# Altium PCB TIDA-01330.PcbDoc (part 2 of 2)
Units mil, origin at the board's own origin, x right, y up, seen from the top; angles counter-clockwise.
Board outline 4950 x 3950 mil, 2 copper layers (Top Layer, Bottom Layer), stack 62.2 mil thick; 84 components, 65 nets, 268 pads, 356 vias.
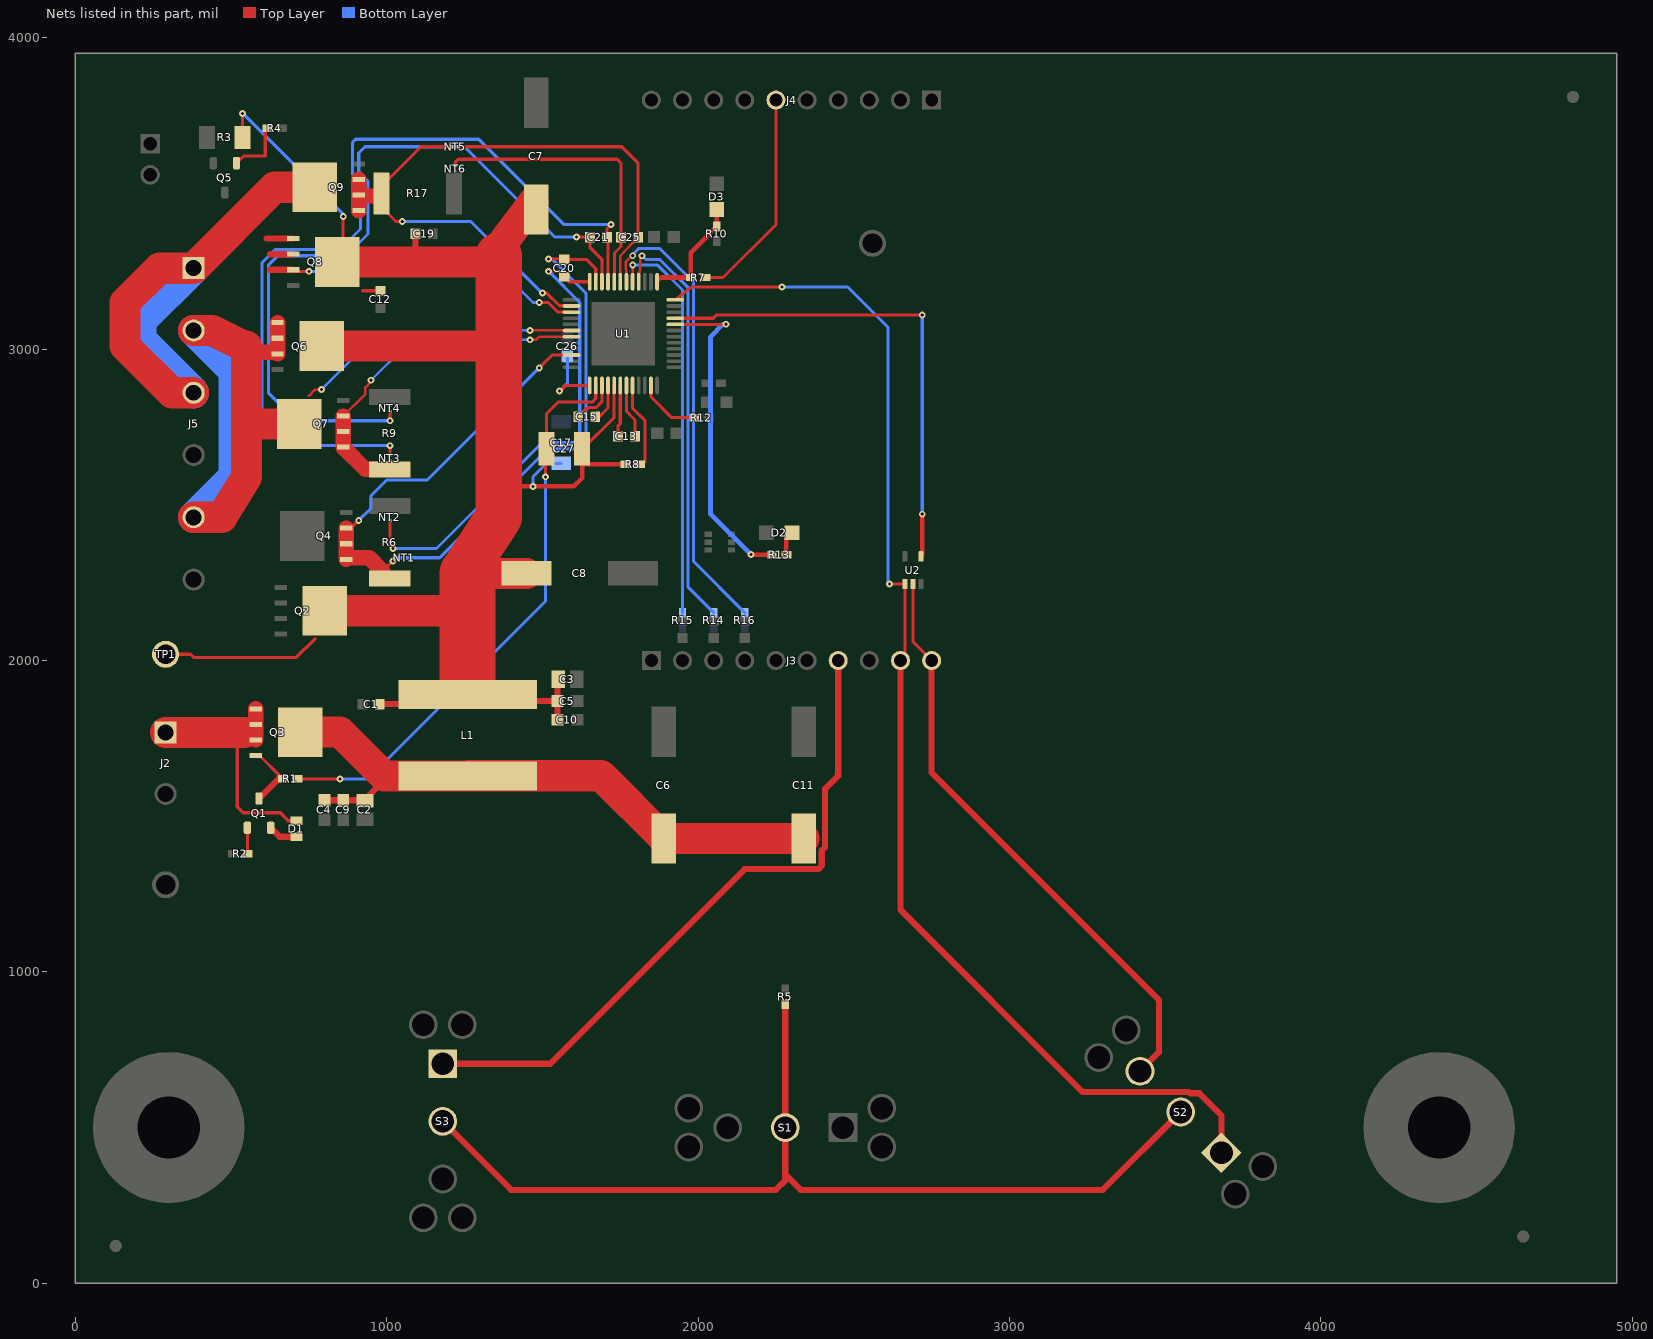
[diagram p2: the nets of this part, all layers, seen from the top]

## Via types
v1: diameter 22, hole 10, Top Layer to Bottom Layer, 318 vias
v2: diameter 19.68, hole 7.87, Top Layer to Bottom Layer, 25 vias
v3: diameter 39.37, hole 19.68, Top Layer to Bottom Layer, 12 vias
v4: diameter 26, hole 10, Top Layer to Bottom Layer, 1 vias

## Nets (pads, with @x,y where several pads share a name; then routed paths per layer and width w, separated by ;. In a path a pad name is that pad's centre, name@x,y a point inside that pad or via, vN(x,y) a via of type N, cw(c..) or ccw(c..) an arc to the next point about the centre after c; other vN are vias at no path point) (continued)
MOT_B: J5.2 J5.5 Q6.1 Q6.2 Q6.3 Q7.5 U1.30 | length 2850
  Top Layer w8: 750,2850 770,2870 v1(790,2870) ; v1(1460,3060) U1.30@1593.5,3060
  Top Layer w50: 520,2990 550,2990 Q6.3@649.57,2990 ; Q6.3@649.57,2985 Q6.2@649.57,3035 Q6.1@649.57,3085
  Top Layer w100: J5.5@380,2460 470,2460 550,2590 ; J5.2@380,3060 440,3060 539.45,3010 ; 550,2600 550,2990 550,3010 ; 560,2760 Q7.5@718.31,2760
  Bottom Layer w8: v1(790,2870) 943.13,3023.13 1356.99,3023.13 1393.86,3060 v1(1460,3060)
  Bottom Layer w100: J5.5@380,2460 510,2590 510,2930 J5.2@380,3060
MOT_C: J5.1 J5.3 Q8.1 Q8.2 Q8.3 Q9.5 U1.27 | length 2902.9
  Top Layer w10: Q8.3@704.57,3250 v1(750,3250) ; v1(1490,3150) 1518.91,3150 1550.01,3118.9 U1.27@1593.66,3118.9 U1.27@1592.76,3119.8
  Top Layer w20: 615,3355 Q8.1@699.57,3355 ; 625,3255 Q8.3@699.57,3255 ; 625,3305 Q8.2@699.57,3305
  Top Layer w100: J5.3@380,2860 310,2860 160,3010 160,3150 270,3260 J5.1@380,3260 640,3520 Q9.5@768.31,3520
  Bottom Layer w10: v1(750,3250) 1370,3250 1470,3150 v1(1490,3150)
  Bottom Layer w100: J5.3@380,2860 210,3030 210,3090 J5.1@380,3260
NetC13_1: C13.1 U1.43 | length 175.1
  Top Layer w10: U1.43@1769.84,2883.66 1769.84,2800.16 1797.56,2772.44 C13.1@1797.56,2720
NetC13_2: C13.2 U1.42 | length 166.9
  Top Layer w10: C13.2@1742.44,2720 1742.44,2752.44 1750.16,2760.16 U1.42@1750.16,2883.66
NetC15_1: C15.1 U1.39 | length 148.9
  Top Layer w10: C15.1@1614.88,2782.44 1642.44,2810 1646.87,2810 1648.92,2812.05 1672.05,2812.05 1691.1,2831.1 U1.39@1691.1,2883.66
NetC15_2: C15.2 U1.40 | length 125.4
  Top Layer w10: C15.2@1670,2782.44 1682.44,2782.44 1710.79,2810.79 U1.40@1710.79,2883.66
NetC26_1: C26.1 U1.37 | length 227.5
  Top Layer w10: v1(1555.28,2865.28) 1573.66,2883.66 U1.37@1651.73,2883.66
  Bottom Layer w10: v1(1555.28,2865.28) 1580,2890 C26.1@1580,2978.5
NetD1_2: D1.2 Q1.2 | length 94.3
  Top Layer w20: Q1.2@627.4,1462.76 655.75,1434.41 D1.2@710,1434.41
NetD2_2: D2.2 R13.2 | length 52.3
  Top Layer w15: R13.2@2283.62,2340 D2.2@2283.62,2392.28
NetQ1_1: Q1.1 R2.1 | length 81.7
  Top Layer w10: R2.1@552.6,1381.02 Q1.1@552.6,1462.76
NetQ1_3: Q1.3 Q3.4 R1.2 | length 197
  Top Layer w10: Q3.4@579.57,1695 591.38,1695 R1.2@659.57,1626.81
  Top Layer w20: Q1.3@590,1557.24 R1.2@652.76,1620
NetQ5_1: Q5.1 R4.2 | length 198.4
  Top Layer w10: Q5.1@517.4,3597.24 540.16,3620 610,3620 610,3710 R4.2@616.38,3710
NetR5_2: R5.2 S1.2 S2.2 S3.2 | length 3164.2
  Top Layer w20: S3.2@1180,520 1400,300 2250,300 2280,330 2280,350 ; R5.2@2280,896.38 S1.2@2280,500 2280,350 ; S2.2@3550,550 3300,300 2330,300 2280,350
NetR8_1: R8.1 U1.44 | length 274.6
  Top Layer w10: U1.44@1789.53,2883.66 1789.53,2810.47 1830,2770 1830,2640 R8.1@1820,2630
NetR14_2: R14.2 U1.16 | length 1359
  Top Layer w8: U1.16@1811.12,3218.24 U1.16@1809.21,3216.34 1809.21,3244.44 1812.93,3248.15 1812.93,3253.74 1813.83,3254.65 1813.83,3293.83 v1(1820,3300)
  Bottom Layer w10: v1(1820,3300) 1832.13,3287.87 1877.4,3287.87 1967.87,3197.4 1967.87,2235.75 R14.2@2050,2153.62
NetR15_2: R15.2 U1.17 | length 1285.4
  Top Layer w8: v1@1789.53,3269.53 U1.17@1789.53,3216.34 U1.17@1791.43,3218.24
  Bottom Layer w10: v1(1790,3270) 1870,3270 1950,3190 R15.2@1950,2153.62
NetR16_2: R16.2 U1.18 | length 1480.2
  Top Layer w8: U1.18@1771.75,3218.24 U1.18@1769.84,3216.34 1769.84,3255.09 1767.13,3257.81 1767.13,3279.47 1787.65,3300 v1(1790,3300)
  Bottom Layer w10: v1(1790,3300) 1790,3303.76 1810.11,3323.87 1876.13,3323.87 1985.75,3214.25 1985.75,2317.87 R16.2@2150,2153.62
NFAULT: R13.1 U1.8 | length 1050.1
  Top Layer w10: U1.8@1926.34,3079.53 v1@2089.53,3079.53
  Top Layer w15: v1(2170,2340) R13.1@2236.38,2340
  Bottom Layer w15: v1(2090,3080) 2079.84,3080 2040,3040.16 2040,2470 v1(2170,2340)
NRESET: J4.6 R7.2 | length 696.8
  Top Layer w10: R7.2@2023.62,3230 2080,3230 2250,3400 J4.6@2250,3800
NSCS: U1.9 U2.4 | length 1575.7
  Top Layer w10: U1.9@1926.34,3099.21 2049.21,3099.21 2060,3110 v1(2720,3110)
  Top Layer w15: U2.4@2715.59,2334.29 2720,2338.7 v1(2720,2470)
  Bottom Layer w10: v1(2720,2470) v1(2720,3110)
PVDD: C1.1 C3.1 C5.1 C7.1 C8.1 C10.1 C12.1 C17.1 C19.1 C27.2 L1.2 Q2.5 Q6.5 Q8.5 R3.1 R8.2 TP1.1 U1.41 | length 6091.8
  Top Layer w10: TP1.1@290,2020 370,2020 380,2010 710,2010 770,2070 ; R3.1@537.09,3680 v1(537.09,3757.09) ; Q8.5@860,3298.31 860,3426.24 v1(860.56,3425.68) ; 922.44,3187.56 C12.1@980,3187.56 ; C27.2@1627.75,2679.34 C27.2@1627.09,2680 1630,2680 1730.47,2780.47 U1.41@1730.47,2883.66
  Top Layer w15: 1369.19,2559.19 v1(1470,2559.19) 1600.81,2559.19 1627.75,2586.13 ; 1627.75,2590 C27.2@1627.75,2679.34 ; C27.2@1627.75,2630 R8.2@1766.38,2630
  Top Layer w20: C1.1@977.56,1860 L1.2@1229.09,1860 ; 1092.44,3287.56 C19.1@1092.44,3370 ; L1.2@1280.91,1870 C5.1@1548.5,1870 ; C10.1@1548.5,1810 C5.1@1548.5,1870 ; C3.1@1550.47,1940 1548.5,1938.03 C5.1@1548.5,1870
  Top Layer w100: Q6.5@791.69,3010 1350,3010 ; Q2.5@801.69,2160 1260,2160 ; Q8.5@841.69,3280 1340,3280 ; 1260,2280 C8.1@1448.74,2280 ; 1380,3350 C7.1@1470,3470
  Top Layer w150: 1250,2290 1360,2460 1360,3300
  Top Layer w180: 1260,1940 1260,2160 1260,2280
  Bottom Layer w10: v1(537.09,3757.09) 860.56,3433.61 v1(860.56,3425.68) ; v1(1470,2559.19) 1470,2590 1513.07,2633.07 C17.1@1560,2633.07
PWRGD: D3.1 R7.1 R10.1 U1.13 | length 368.3
  Top Layer w10: U1.13@1868.27,3216.34 1881.93,3230
  Top Layer w15: 1881.93,3230 R7.1@1976.38,3230 1976.38,3310 2032.82,3366.44 2032.82,3368.49 2057.94,3393.62 R10.1@2060,3393.62 D3.1@2060,3448.66
S1_N: C20.1 NT1.1 U1.23 | length 1575.2
  Top Layer w10: v1(1520,3290) C20.1@1567.56,3290 ; C20.1@1570,3287.56 1642.44,3287.56 1671.42,3258.58 U1.23@1671.42,3216.34
  Bottom Layer w10: NT1.1@1066.31,2330 1170,2330 1510,2671.72 1510,2680 1610,2680 1610,2681.72 1640,2711.72 1640,3180 1530,3290 v1(1520,3290)
S1_P: C20.2 NT2.1 U1.24 | length 1558.8
  Top Layer w10: NT2.1@1010,2450 1010,2370 v1(1020,2360) ; v1(1520,3250) 1552.44,3250 C20.2@1570,3232.44 1586.1,3216.34 U1.24@1650.14,3216.34
  Bottom Layer w10: v1(1020,2360) 1160,2360 1470,2670 1500,2700 1600,2700 1620,2720 1620,3150 v1(1520,3250)
S2_N: C21.1 NT3.1 U1.21 | length 2774.6
  Top Layer w10: NT3.1@1010,2660 v1(1010,2690) ; U1.21@1711.1,3210.59 1711.1,3356.46 C21.1@1707.56,3360 1707.56,3387.56 v1(1720,3400)
  Bottom Layer w10: v1(1010,2690) 680,2690 600,2770 600,3278.28 641.72,3320 850,3320 915.86,3385.86 915.86,3535.86 890,3561.72 890,3664.14 900,3674.14 1295.86,3674.14 1570,3400 v1(1720,3400)
S2_P: C21.2 NT4.1 U1.22 | length 2531.6
  Top Layer w10: v1(1010,2770) NT4.1@1010,2800 ; v1(1610,3360) C21.2@1652.44,3360 1652.44,3327.56 1691.1,3288.9 U1.22@1691.1,3216.34
  Bottom Layer w10: v1(1010,2770) 710,2770 620,2860 620,3270 650,3300 870,3300 940,3370 940,3540 910,3570 910,3630 930,3650 1250,3650 1540,3360 v1(1610,3360)
S3_N: C25.1 NT5.1 U1.19 | length 1001.5
  Top Layer w8: U1.19@1750.16,3216.34 1750.16,3298.78 ; 1751.38,3300 C25.1@1807.56,3360
  Top Layer w10: NT5.1@1230,3650 1755.12,3650 1807.56,3597.56 C25.1@1807.56,3360
S3_P: C25.2 NT6.1 U1.20 | length 940.8
  Top Layer w10: NT6.1@1220,3590 1220,3600 1230,3610 1740,3610 1752.44,3597.56 C25.2@1752.44,3360 1752.44,3329.69 1731.38,3308.62 U1.20@1731.38,3217.24
SL_A: NT1.2 Q4.1 Q4.2 Q4.3 R6.2 U1.34 | length 1290.6
  Top Layer w10: Q4.3@870.43,2425 885,2425 v1(910,2450) ; R6.2@986.93,2286.93 v1(1020,2320) ; v1(1490,2940) 1531.1,2981.1 U1.34@1593.66,2981.1
  Top Layer w50: Q4.3@870.43,2425 Q4.2@870.43,2375 Q4.1@870.43,2325 875.43,2330 943.86,2330 R6.2@986.93,2286.93
  Bottom Layer w10: v1(910,2450) 950,2490 950,2530 1000,2580 1130,2580 v1(1490,2940) ; v1(1020,2320) 1030,2330 NT1.2@1046.31,2330
SL_B: NT3.2 Q7.1 Q7.2 Q7.3 R9.2 U1.31 | length 1132.9
  Top Layer w8: Q7.3@860.43,2785 931.2,2855.76 931.2,2876.65 950,2895.45 v1(950,2900) ; v1(1460,3030) 1480,3030 1490.16,3040.16 U1.31@1593.66,3040.16
  Top Layer w50: Q7.3@860.43,2785 Q7.2@860.43,2735 Q7.1@860.43,2685 931.57,2613.86 R9.2@1010,2613.86
  Bottom Layer w8: v1(950,2900) 1057.25,3007.25 1363.56,3007.25 1386.31,3030 v1(1460,3030)
SL_C: NT5.2 Q9.1 Q9.2 Q9.3 R17.2 U1.26 | length 1213.3
  Top Layer w10: R17.2@983.86,3456.14 1030,3410 v1(1050,3410) ; R17.2@983.86,3500 983.86,3523.86 1110,3650 NT5.2@1210,3650 ; v1(1500,3180) 1514.18,3180 1554.7,3139.49 1592.76,3139.49 U1.26@1593.66,3138.58
  Top Layer w50: Q9.1@910.43,3445 Q9.2@910.43,3495 ; Q9.3@910.43,3545 Q9.2@910.43,3495 ; R17.2@980,3490 Q9.2@910.43,3495
  Bottom Layer w10: v1(1050,3410) 1270,3410 v1(1500,3180)
TILT+: J3.9 S2.1 U1.12 U2.1 | length 4104.3
  Top Layer w10: U1.12@1926.34,3158.27 1980,3200 v1(2270,3200) ; v1(2614.29,2245.71) U2.1@2664.41,2245.71 2664.41,2014.41 J3.9@2650,2000
  Top Layer w20: J3.9@2650,2000 2650,1200 3235.87,614.13 3576.57,614.13 3580.7,610 3610,610 3680.84,539.16 S2.1@3680.84,419.16
  Bottom Layer w10: v1(2270,3200) 2480,3200 2610,3070 2610,2250 v1(2614.29,2245.71)
TILT-: J3.10 S2.3 U2.2 | length 1917.3
  Top Layer w10: U2.2@2690,2245.71 2690,2060 J3.10@2750,2000
  Top Layer w20: J3.10@2750,2000 2750,1640 3480,910 3480,741.69 S2.3@3419.16,680.84
UP: J3.7 S3.1 | length 2161.7
  Top Layer w20: S3.1@1180,705.04 1525.04,705.04 2150.16,1330.16 2386.77,1330.16 2397.24,1340.63 2397.24,1390 2407.87,1400.63 2407.87,1587.87 2450,1630 J3.7@2450,2000
VBATT: D1.1 J2.1 Q3.1 Q3.2 Q3.3 | length 776.8
  Top Layer w10: 520,1745.91 520,1530 539.02,1510.98 657.91,1510.98 683.31,1485.59 D1.1@710,1485.59
  Top Layer w50: Q3.3@579.57,1745 Q3.2@579.57,1795 Q3.1@579.57,1845
  Top Layer w100: J2.1@290,1768.43 542.52,1768.43
VCPH: C27.1 R1.1 U1.38 | length 1853.3
  Top Layer w10: R1.1@713.62,1620 v1(850,1620) ; v1(1510,2590) C27.1@1510,2677.09 ; C27.1@1512.91,2680 1512.91,2792.91 1550,2830 1660,2830 1671.42,2841.42 U1.38@1671.42,2883.66
  Bottom Layer w10: v1(850,1620) 940,1620 1510,2190 v1(1510,2590)
VFILT: C2.1 C4.1 C6.1 C9.1 C11.1 L1.1 Q3.5 | length 1990.8
  Top Layer w20: C4.1@800,1551.5 C9.1@860,1551.5 928.03,1551.5 990.91,1614.37 990.91,1629.09
  Top Layer w100: Q3.5@721.69,1770 850,1770 990.91,1629.09 L1.1@1260,1629.09 ; L1.1@1260.91,1630 1688.74,1630 C6.1@1890,1428.74 C11.1@2340,1428.74
WAKE: R12.1 U1.47 | length 202.4
  Top Layer w10: U1.47@1848.58,2883.66 1848.58,2846.69 1915.28,2780 R12.1@1986.38,2780
pads on no net: D4.4 FID1.1 FID2.1 FID3.1 J4.7 MH1.1 MH2.1 S1.S1 S1.S2 S1.S3 S1.S4 S2.S1 S2.S2 S2.S3 S2.S4 S3.S1 S3.S2 S3.S3 S3.S4
copper on no net:
  other v3: 300,341.54 4380,341.54 162.77,420.77 437.23,420.77 4242.77,420.77 4517.23,420.77 162.77,579.23 437.23,579.23 4242.77,579.23 4517.23,579.23 300,658.46 4380,658.46

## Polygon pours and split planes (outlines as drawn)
GND on Bottom Layer "BOTTOM_LAYER_GND_P008" (solid, remove dead copper, pour order 8): 50,50 4900,50 4900,3900 50,3900 50,50
GND on Top Layer "TOP_LAYER_GND_P020" (solid, remove dead copper, pour order 20): 10,10 10,3940 4940,3940 4940,10 10,10
MOT_C on Top Layer "TOP_LAYER_MOT_C_P018" (solid, remove dead copper, pour order 18): 660,3370 660,3240 410,3240 550,3370

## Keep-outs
Keep-Out Layer:
  text ".Layer_Name" at 577,-858.49 h60

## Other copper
Top Layer:
  text ".Layer_Name" at 577,-858.49 h60
Bottom Layer:
  text ".Layer_Name" at 577,-858.49 h60

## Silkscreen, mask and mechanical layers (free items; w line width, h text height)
Top Overlay:
  region: 4120,3160 3820,3160 3820,3060 4120,3060
  lines w10: 100,1360 2780,1360 ; 100,1880 100,3470 ; 100,3860 2790,3860 2790,3720 2790,1360
  text "-LED+" at 90,3520 h72.83 r90
  text "TIDA-01330" at 3040,3070 h150
  text "+" at 50,1750 h100
  text "-" at 50,1550 h100
  text ".Layer_Name" at 577,-858.49 h60
Bottom Overlay:
  text ".Layer_Name" at 577,-858.49 h60
Top Paste:
  text ".Layer_Name" at 577,-858.49 h60
Bottom Paste:
  text ".Layer_Name" at 577,-858.49 h60
Top Solder:
  text ".Layer_Name" at 577,-858.49 h60
  text ".Layer_Name" at 577,-858.49 h60
Bottom Solder:
  text ".Layer_Name" at 577,-858.49 h60
Drill Guide:
  text ".Layer_Name" at 577,-858.49 h60
M1 Board Outline:
  the board outline again, w10
  text ".Layer_Name" at 577,-858.49 h60
M2 Board Dimensions:
  rectangle: 125,-400 500,-275
  rectangle: 0,-275 125,-150
  lines w7: 0,-275 1000,-275 ; 125,-400 125,-150 ; 250,-400 250,-150 ; 500,-400 500,-150 ; 750,-400 750,-150 ; 0,-400 0,-150 1000,-150 1000,-400 0,-400
  lines w10: 4950,0 4950,3940
  text ".Layer_Name" at 577,-858.49 h60
M3 3D STEP Top:
  text ".Layer_Name" at 577,-858.49 h60
M4 3D STEP Bottom:
  text ".Layer_Name" at 577,-858.49 h60
M5 Assembly Top:
  lines w10: -292,-930.17 6308,-930.17 ; -292,-726.83 6310,-726.83 ; -292,-523.5 -292,-1133.5 3713,-1133.5 6310,-1133.5 6310,-523.5 -291.5,-523.5 -291.5,-1133.5 1284,-1133.5 ; 2173,-1133.5 2173,-523.5 ; 3440,-726.83 3440,-523.5 ; 4280,-726.83 4280,-523.5 ; 4902,-1140 4902,-937.17
  text "COMPONENTS MARKED 'DNP' SHOULD NOT BE POPULATED." at 1153.5,-318.5 h60
  text "ASSEMBLY VARIANT:" at 1153,-434 h60
  text ".VariantName" at 2189,-434 h60
  text "PCB VIEWED FROM TOP SIDE" at -228.5,-655.67 h60
  text "BOARD #:" at 2248,-655.67 h60
  text ".PRJ_Number" at 2793.5,-655.67 h60
  text "REV:" at 3638,-655.67 h60
  text ".PCB_Rev" at 3929.5,-655.67 h60
  text "SVN REV:" at 4476,-655.67 h60
  text ".VersionControl_RevNumber" at 4982,-655.67 h60
  text "TID #:" at 2248,-859 h60
  text ".TID" at 2793.5,-859 h60
  text "PLOT NAME =" at -228.5,-1064.34 h60
  text ".plot_File_Name" at 577,-1064.34 h60
  text "GENERATED    :" at 2250,-1064.34 h60
  text ".Print_Date" at 3119.5,-1064.34 h60
  text ".Print_Time" at 3848.5,-1064.34 h60
  text "TEXAS INSTRUMENTS" at 5113,-1064.34 h60
M6 Assembly Bottom:
  lines w10: -292.5,-727.33 6309.5,-727.33 ; -290.5,-930.67 6309.5,-930.67 ; 1115.5,-1140.5 1115.5,-937.67 ; 1737.5,-727.33 1737.5,-524 ; 2577.5,-727.33 2577.5,-524 ; 3844.5,-1134 3844.5,-524 ; 4733.5,-1134 6309,-1134 6309,-524 -292.5,-524 -292.5,-1134 2304.5,-1134 6309.5,-1134 6309.5,-524
  text "COMPONENTS MARKED 'DNP' SHOULD NOT BE POPULATED." at 6102,-318 h60
  text ".VariantName" at 5058,-434 h60
  text "ASSEMBLY VARIANT:" at 6097,-434 h60
  text ".VersionControl_RevNumber" at 1035.5,-656.17 h60
  text "SVN REV:" at 1541.5,-656.17 h60
  text ".PCB_Rev" at 2088,-656.17 h60
  text "REV:" at 2379.5,-656.17 h60
  text ".PRJ_Number" at 3224,-656.17 h60
  text "BOARD #:" at 3769.5,-656.17 h60
  text "PCB VIEWED FROM BOTTOM SIDE" at 6246,-656.17 h60
  text ".TID" at 3224,-859.5 h60
  text "TID #:" at 3769.5,-859.5 h60
  text "TEXAS INSTRUMENTS" at 904.5,-1064.84 h60
  text ".Print_Time" at 2169,-1064.84 h60
  text ".Print_Date" at 2898,-1064.84 h60
  text "GENERATED    :" at 3767.5,-1064.84 h60
  text ".plot_File_Name" at 5440.5,-1064.84 h60
  text "PLOT NAME =" at 6246,-1064.84 h60
M9 Title Sheet:
  drawing of 57 lines, arcs and shapes, not listed
  text "1" at 739.84,8036.5 h70
  text "2" at 3235.5,8036.5 h70
  text "3" at 5724.84,8036.5 h70
  text "4" at 8231.51,8036.5 h70
  text "5" at 10730.5,8036.5 h70
  text "6" at 13235.5,8036.5 h70
  text "A" at -416.5,6893.5 h70
  text "A" at 14383.5,6893.5 h70
  text "B" at -416.5,4513.5 h70
  text "B" at 14383.5,4513.5 h70
  text "C" at -416.5,2138.5 h70
  text "C" at 14383.5,2138.5 h70
  text "PROJECT TITLE:" at 11343.5,277.5 h45
  text ".PRJ_Title" at 11393.5,144.17 h70
  text "DESIGNED FOR:" at 11343.5,-23.5 h45
  text ".PRJ_Customer" at 11393.5,-163.5 h70
  text "D" at -416.5,-231.5 h70
  text "D" at 14383.5,-231.5 h70
  text "FILE NAME:" at 11343.5,-323.5 h45
  text ".PCB_File_Name_No_Path" at 11393.5,-443.5 h70
  text "Texas Instruments (TI) and/or its licensors do not warrant the accuracy or completeness of this specification" at 6374,-605.34 h45
  text "ENGINEER:" at 11343.5,-613.5 h45
  text "LAYOUT BY:" at 12848.5,-613.5 h45
  text "or any information contained therein. TI and/or its licensors do not warrant that this design will meet" at 6329.01,-718 h45
  text ".PRJ_Engineer" at 11393.5,-768.49 h70
  text ".PCB_Layout" at 12899,-768.49 h70
  text "the specifications, will be suitable for your application or fit for any particular purpose, or will operate in" at 6329.01,-830.67 h45
  text ".Layer_Name" at 577,-858.49 h60
  text "ALTIUM DESIGNER VERSION:" at 12848.5,-923.5 h45
  text "an implementation. TI and/or its licensors do not warrant that the design is production worthy. You should" at 6329.01,-943.33 h45
  text "completely validate and test your design implementation to confirm the system functionality for your application." at 6374,-1056 h45
  text ".print_Scale" at 11393.5,-1056.83 h70
  text ".Application_BuildNumber" at 12899,-1056.83 h70
  text "1" at 739.84,-1263.5 h70
  text "2" at 3235.5,-1263.5 h70
  text "3" at 5724.84,-1263.5 h70
  text "4" at 8231.51,-1263.5 h70
  text "5" at 10730.5,-1263.5 h70
  text "6" at 13235.5,-1263.5 h70
M10 Fab Notes:
  drawing of 173 lines, arcs and shapes, not listed
  text "DESIGN INFORMATION" at 12378.02,6201 h60
  text "MIN. TRACK WIDTH:" at 11733.46,6021 h60
  text "8" at 12829.7,6021 h60
  text "MIL" at 12984.46,6021 h60
  text "MIN. CLEARANCE:" at 11733.46,5889 h60
  text "0.2" at 12769.7,5889 h60
  text "mm" at 12984.46,5889 h60
  text "MIN. VIA PAD SIZE:" at 11733.46,5757 h60
  text "24" at 12799.71,5757 h60
  text "MIL" at 12984.46,5757 h60
  text "0.05mm (2MIL)" at 12428.46,5615.29 h60
  text "MINIMUM ANNULAR RING" at 11404.23,5611 h60
  text "EXTERNAL" at 13136.46,5611 h60
  text "PER" at 11604.23,5493 h60
  text "IPC-D-275 CLASS 2 LEVEL C" at 11824.23,5493 h60
  text "MIL, HOLES" at 13312.46,5380.71 h60
  text "+/-" at 12920,5380 h60
  text "+/-" at 13774,5380 h60
  text "REGISTRATION TOLERANCES:" at 11404.23,5375 h60
  text "METAL" at 12604,5375 h60
  text "5" at 13180.2,5375 h60
  text "3" at 14013.2,5375 h60
  text "MIL" at 14129.46,5375 h60
  text "+/-" at 13774,5262 h60
  text "HOLE SIZE TOLERANCE (UNLESS OTHERWISE SPECIFIED):" at 11404.23,5257 h60
  text "3" at 14013.2,5257 h60
  text "MIL" at 14129.46,5257 h60
  text "MATERIAL:" at 11329.46,5047.54 h60
  text "FR-4 High Tg" at 12315.9,4907.21 h60
  text "FR-408" at 11750.46,4898.64 h60
  text "OTHER" at 13238.46,4898.64 h60
  text "X" at 12161,4895 h60
  text "62 MIL (1.6mm) +/-10%" at 12070.56,4735.92 h60
  text "THICKNESS:" at 11404.23,4731.64 h60
  text "X" at 11942.4,4731.64 h60
  text "OTHER" at 13355.46,4731.64 h60
  text "TOLERANCE:" at 11404.23,4573.64 h60
  text "X" at 12243.53,4573.64 h60
  text "ANSI IPC-6012 TYPE 3 CLASS 2" at 12430.48,4573.64 h60
  text "OTHER +/-" at 12430.46,4417.64 h60
  text "BOW & TWIST:" at 11404.23,4260.64 h60
  text "X" at 12243.53,4260.64 h60
  text "ANSI IPC-6012 TYPE 3 CLASS 2" at 12430.48,4260.64 h60
  text "OTHER +/-" at 12430.46,4102.13 h60
  text "DRILLING:" at 11329.46,3963.64 h60
  text "REFERENCE:" at 11404.23,3846.64 h60
  text "X" at 12052.46,3846.64 h60
  text "AS SHOWN" at 12239.46,3846.64 h60
  text "X" at 12953.46,3846.64 h60
  text "NC_DRILL FILES" at 13090.46,3846.64 h60
  text "PTH COPPER THICKNESS:" at 11404.23,3688.64 h60
  text "X" at 12534.46,3688.64 h60
  text "20-30 um" at 12671.46,3688.64 h60
  text "OTHER" at 13388.46,3688.64 h60
  text "BOARD FINISH:" at 11329.46,3529.64 h60
  text "SILKSCREEN:" at 11484.68,3411.64 h60
  text "X" at 12433.46,3411.64 h60
  text "TOP" at 12559.46,3411.64 h60
  text "X" at 12943.46,3411.64 h60
  text "BOTTOM" at 13070.46,3411.64 h60
  text "SILKSCREEN COLOR:" at 11484.68,3244.64 h60
  text "X" at 12432.42,3244.64 h60
  text "WHITE" at 12559.46,3244.64 h60
  text "OTHER" at 13070.46,3244.64 h60
  text "X" at 12563.42,3085.44 h60
  text "GREEN" at 12690.46,3085.44 h60
  text "OTHER" at 13308.46,3085.44 h60
  text "SOLDER RESIST COLOR:" at 11484.68,3074.64 h60
  text "X" at 12563.42,2915.44 h60
  text "MATTE" at 12690.46,2915.44 h60
  text "SEMI-GLOSS" at 13308,2914.8 h60
  text "IMMERSION GOLD (ENIG)" at 12390.46,2726.92 h60
  text "ENEPIG" at 13728,2723.64 h60
  text "SURFACE FINISH:" at 11329.46,2722.64 h60
  text "X" at 12203.51,2722.64 h60
  text "IMM. TIN/SILVER OR EQUIV" at 11659,2565.64 h60
  text "OTHER" at 13090.46,2565.64 h60
  text "ARRAY/PANEL:" at 11329.46,2386.64 h60
  text "CUT AND TRIM PER M1 BOARD OUTLINE" at 12390.46,2382.35 h60
  text "N.C. ROUTE" at 12390.46,2230.64 h60
  text "X" at 13069.46,2230.64 h60
  text "V. SCORE" at 13256.46,2230.64 h60
  text "CERTIFICATION:" at 11329.46,2093.64 h60
  text "MATERIALS AND WORKMANSHIP FOR ALL PCBS" at 12054.46,2093.64 h60
  text "TO MEET OR EXCEED THE REQUIREMENTS OF:" at 12054.46,1995.64 h60
  text "X" at 11680.96,1859.13 h60
  text "ANSI IPC-A-600F CLASS ->" at 11819.96,1859.13 h60
  text "X" at 13459.02,1859.13 h60
  text "2" at 13577.96,1859.14 h60
  text "1" at 13262.96,1857.64 h60
  text "3" at 13931.96,1857.64 h60
  text "X" at 12495.02,1699.64 h60
  text "RoHS" at 12631.96,1699.64 h60
  text "OTHER" at 13276.36,1699.64 h60
  text "PER ORDER" at 13673.42,1699.64 h60
  text "ALL BOARDS MUST MEET OR EXCEED UL94-V0 REQUIREMENTS." at 11357,1534 h60
  text "PCB MUST BEAR THE UL94V-0 UL REGISTERED MATERIAL ID NUMBER" at 11357,1414 h60
  text "ADDITIONAL REQUIREMENTS:" at 11329.46,1240.64 h60
  text "MICROSECTION:" at 11404.23,1125.64 h60
  text "YES" at 12309.96,1125.64 h60
  text "REQUIRED" at 13171.46,969.49 h60
  text "BARE BOARD ELEC. TEST:" at 11404.23,966.64 h60
  text "NONE" at 12709.96,966.64 h60
  text "X" at 13044.46,966.64 h60
  text "PER ORDER" at 13763.46,966.64 h60
  text ".Layer_Name" at 577,-858.49 h60
M11 Gerber Information:
  lines w10: -292,-930.17 6308,-930.17 ; -292,-726.83 6310,-726.83 ; -292,-523.5 -292,-1133.5 3713,-1133.5 6310,-1133.5 6310,-523.5 -291.5,-523.5 -291.5,-1133.5 1284,-1133.5 ; 2173,-1133.5 2173,-523.5 ; 3440,-726.83 3440,-523.5 ; 4280,-726.83 4280,-523.5 ; 4902,-1140 4902,-937.17
  text "ALL ARTWORK VIEWED FROM TOP SIDE" at -228.5,-655.67 h60
  text "BOARD #:" at 2248,-655.67 h60
  text ".PRJ_Number" at 2793.5,-655.67 h60
  text "REV:" at 3638,-655.67 h60
  text ".PCB_Rev" at 3929.5,-655.67 h60
  text "SVN REV:" at 4476,-655.67 h60
  text ".VersionControl_RevNumber" at 4982,-655.67 h60
  text "LAYER NAME =" at -228.5,-858.49 h60
  text "TID #:" at 2248,-859 h60
  text ".TID" at 2793.5,-859 h60
  text "PLOT NAME =" at -228.5,-1064.34 h60
  text ".plot_File_Name" at 577,-1064.34 h60
  text "GENERATED    :" at 2250,-1064.34 h60
  text ".Print_Date" at 3119.5,-1064.34 h60
  text ".Print_Time" at 3848.5,-1064.34 h60
  text "TEXAS INSTRUMENTS" at 5113,-1064.34 h60
M12 Stackup:
  drawing of 191 lines, arcs and shapes, not listed
  text "Layer" at 9140.34,7540 h60
  text "Name" at 9550.26,7540 h60
  text "Material" at 10480,7540 h60
  text "Thickness" at 11339.77,7540 h60
  text "Constant" at 11989.6,7540 h60
  text "Board Layer Stack" at 12559.46,7540 h60
  text "1" at 9140.34,7420 h60
  text "Top Overlay" at 9550.26,7420 h60
  text "2" at 9140.34,7300 h60
  text "Top Solder" at 9550.26,7300 h60
  text "Solder Resist" at 10480,7300 h60
  text "0.40mil" at 11339.77,7300 h60
  text "3.5" at 11989.6,7300 h60
  text "3" at 9140.34,7180 h60
  text "Top Layer" at 9550.26,7180 h60
  text "Copper" at 10480,7180 h60
  text "1.40mil" at 11339.77,7180 h60
  text "4" at 9140.34,7060 h60
  text "Dielectric1" at 9550.26,7060 h60
  text "FR-4" at 10480,7060 h60
  text "59.20mil" at 11339.77,7060 h60
  text "4.8" at 11989.6,7060 h60
  text "5" at 9140.34,6940 h60
  text "Bottom Layer" at 9550.26,6940 h60
  text "Copper" at 10480,6940 h60
  text "1.40mil" at 11339.77,6940 h60
  text "6" at 9140.34,6820 h60
  text "Bottom Solder" at 9550.26,6820 h60
  text "Solder Resist" at 10480,6820 h60
  text "0.40mil" at 11339.77,6820 h60
  text "3.5" at 11989.6,6820 h60
  text "7" at 9140.34,6700 h60
  text "Bottom Overlay" at 9550.26,6700 h60
  text ".Layer_Name" at 577,-858.49 h60
M13 Component Bodies Top:
  text ".Layer_Name" at 577,-858.49 h60
M14 Component Bodies Bottom:
  text ".Layer_Name" at 577,-858.49 h60
M15 Courtyards Top:
  text ".Layer_Name" at 577,-858.49 h60
M16 Courtyards Bottom:
  text ".Layer_Name" at 577,-858.49 h60
Drill Drawing:
  circle w10: c6068.65,3754.18 r22.05
  circle w10: c6068.65,3654.97 r13.23
  circle w10: c6068.65,3654.97 r22.05
  lines w10: 6046.6,3048.68 6057.63,3048.68 6057.63,3037.65 6079.68,3037.65 6079.68,3048.68 6090.7,3048.68 6090.7,3070.72 6079.68,3070.72 6079.68,3081.75 6057.63,3081.75 6057.63,3070.72 6046.6,3070.72 6046.6,3048.68 ; 6046.6,3136.86 6068.65,3147.89 6090.7,3136.86 6079.68,3158.91 6090.7,3180.96 6068.65,3169.93 6046.6,3180.96 6057.63,3158.91 6046.6,3136.86 ; 6046.6,3236.07 6090.7,3236.07 6090.7,3280.17 6046.6,3280.17 6046.6,3236.07 ; 6046.6,3357.33 6068.65,3335.29 6090.7,3357.33 6068.65,3379.38 6046.6,3357.33 ; 6046.6,3434.5 6046.6,3445.52 6057.63,3456.54 6046.6,3467.57 6046.6,3478.59 6057.63,3478.59 6068.65,3467.57 6079.68,3478.59 6090.7,3478.59 6090.7,3467.57 6079.68,3456.54 6090.7,3445.52 6090.7,3434.5 6079.68,3434.5 6068.65,3445.52 6057.63,3434.5 6046.6,3434.5 ; 6046.6,3544.73 6057.63,3544.73 6068.65,3533.71 6079.68,3544.73 6090.7,3544.73 6079.68,3555.75 6090.7,3566.78 6079.68,3566.78 6068.65,3577.8 6057.63,3566.78 6046.6,3566.78 6057.63,3555.75 6046.6,3544.73 ; 6046.6,3842.36 6057.63,3842.36 6057.63,3831.34 6079.68,3831.34 6079.68,3842.36 6090.7,3842.36 6090.7,3864.41 6079.68,3864.41 6079.68,3875.43 6057.63,3875.43 6057.63,3864.41 6046.6,3864.41 6046.6,3842.36 ; 6055.42,3053.09 6062.04,3053.09 6062.04,3046.47 6075.27,3046.47 6075.27,3053.09 6081.88,3053.09 6081.88,3066.31 6075.27,3066.31 6075.27,3072.93 6062.04,3072.93 6062.04,3066.31 6055.42,3066.31 6055.42,3053.09
  lines w12: 6006,3007.89 9115.46,3007.89 ; 6006,3900.79 9115.46,3900.79 ; 6321.13,2908.68 6321.13,4000 ; 6637.88,2908.68 6637.88,4000 ; 7258.9,2908.68 7258.9,4000 ; 7502.83,2908.68 7502.83,4000 ; 7862.73,2908.68 7862.73,4000 ; 8571.88,2908.68 8571.88,4000 ; 6006,2908.68 9115.46,2908.68 9115.46,4000 6006,4000 6006,2908.68
  text "Symbol" at 6065.53,3930.55 h72
  text "Quantity" at 6350.9,3930.55 h72
  text "Finished Hole Size" at 6667.64,3930.55 h72
  text "Plated" at 7288.66,3930.55 h72
  text "Hole Type" at 7532.59,3930.55 h72
  text "Drill Layer Pair" at 7892.49,3930.55 h72
  text "Hole Tolerance" at 8601.64,3930.55 h72
  text "25" at 6350.9,3831.34 h60
  text "7.87mil (0.200mm)" at 6667.64,3831.34 h60
  text "PTH" at 7288.66,3831.34 h60
  text "Round" at 7532.59,3831.34 h60
  text "Top Layer - Bottom Layer" at 7892.49,3831.34 h60
  text "319" at 6350.9,3732.13 h60
  text "10.00mil (0.254mm)" at 6667.64,3732.13 h60
  text "PTH" at 7288.66,3732.13 h60
  text "Round" at 7532.59,3732.13 h60
  text "Top Layer - Bottom Layer" at 7892.49,3732.13 h60
  text "12" at 6350.9,3632.92 h60
  text "19.69mil (0.500mm)" at 6667.64,3632.92 h60
  text "PTH" at 7288.66,3632.92 h60
  text "Round" at 7532.59,3632.92 h60
  text "Top Layer - Bottom Layer" at 7892.49,3632.92 h60
  text "20" at 6350.9,3533.71 h60
  text "40.94mil (1.040mm)" at 6667.64,3533.71 h60
  text "PTH" at 7288.66,3533.71 h60
  text "Round" at 7532.59,3533.71 h60
  text "Top Layer - Bottom Layer" at 7892.49,3533.71 h60
  text "2" at 6350.9,3434.5 h60
  text "43.31mil (1.100mm)" at 6667.64,3434.5 h60
  text "PTH" at 7288.66,3434.5 h60
  text "Round" at 7532.59,3434.5 h60
  text "Top Layer - Bottom Layer" at 7892.49,3434.5 h60
  text "8" at 6350.9,3335.29 h60
  text "51.18mil (1.300mm)" at 6667.64,3335.29 h60
  text "PTH" at 7288.66,3335.29 h60
  text "Round" at 7532.59,3335.29 h60
  text "Top Layer - Bottom Layer" at 7892.49,3335.29 h60
  text "3" at 6350.9,3236.07 h60
  text "63.00mil (1.600mm)" at 6667.64,3236.07 h60
  text "PTH" at 7288.66,3236.07 h60
  text "Round" at 7532.59,3236.07 h60
  text "Top Layer - Bottom Layer" at 7892.49,3236.07 h60
  text "21" at 6350.9,3136.86 h60
  text "72.83mil (1.850mm)" at 6667.64,3136.86 h60
  text "PTH" at 7288.66,3136.86 h60
  text "Round" at 7532.59,3136.86 h60
  text "Top Layer - Bottom Layer" at 7892.49,3136.86 h60
  text "2" at 6350.9,3037.65 h60
  text "200.00mil (5.080mm)" at 6667.64,3037.65 h60
  text "PTH" at 7288.66,3037.65 h60
  text "Round" at 7532.59,3037.65 h60
  text "Top Layer - Bottom Layer" at 7892.49,3037.65 h60
  text "412 Total" at 6350.9,2938.44 h60
  text ".Layer_Name" at 577,-858.49 h60
M17 Embedded Cavity:
  text ".Layer_Name" at 577,-858.49 h60
M18 Embedded Assembly:
  text ".Layer_Name" at 577,-858.49 h60
M19 Embedded Keepout:
  text ".Layer_Name" at 577,-858.49 h60

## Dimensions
0,-400 to 1000,-400 on M2 Board Dimensions
0,0 to 4950,0 on M2 Board Dimensions
-180,3950 to -220,0 on M2 Board Dimensions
